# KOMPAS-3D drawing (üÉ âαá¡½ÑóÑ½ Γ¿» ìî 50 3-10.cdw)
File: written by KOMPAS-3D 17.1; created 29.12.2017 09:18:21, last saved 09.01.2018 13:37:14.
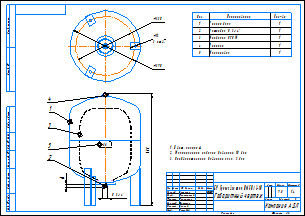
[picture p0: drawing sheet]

Sheet 1: A3, landscape, title-block layout from C:\Лощинин\GRAPHIC.LYT style 1

Title block, sheet 1: name: БР Гранлевел тип НМ 50/3-10 / Габаритный чертеж; mass: 9,8; sheets: 1; sheet format: A3; stored path: K:\АП\20_PKO\02_Насосное направление\Разработка\04_Проекты разные\Баки\КД действующая\Баки Flexcon R\Компас\Чертежи\БР Гранлевел тип НМ 50 1,5-6.cdw; drawn by: Лощинин; checked by: Хантимеров; drawn by, date: 29.12.2017

Views: Вид 1, Снизу
Referenced files in \\Fsk1\files\АП\20_PKO\02_Насосное направление\Разработка\04_Проекты разные\Баки\КД действующая\Баки Flexcon R\Компас\: 50 литров.a3d
Referenced files in C:\Лощинин\: GRAPHIC.LYT
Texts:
  IvAn
  ADL
  БР Гранлевел тип НМ 50/1,5-6
  Цвет: красный
  Максимальное рабочее давление: 10 бар
  Предварительное давление газа: 3 бар
  ACAD_ISO03W100_RGB_223_127_255_SC_0.063_THICK_0.05
  ACAD_ISO03W100_RGB_223_127_255_SC_1_THICK_0.05
  Лит-Масса-Масштаб
  Материал-Предприятие
  Масштаб
  Изм.
  Лист
  № докум.
  Подп.
  Дата
  Лит.
  Разраб.
  Пров.
  Т.контр.
  Курлыкина
  Листов
  Нач.отд.
  Щетинин
  Н.контр.
  Долгов
  Утв.
  Рашидов
  Компания АДЛ
  Изменение
  Номер документа
  Подпись
  Обозначение документа
  Наименование изделия
  Масса изделия по ГОСТ 2.109-73
  Порядковый номер листа
  Общее количество листов в документе
  Характер работы, выполненной лицом, подписавшим документ
  Наименование или индекс предприятия, выпускающего документ
  Инв. № подл.
  Подп. и дата
  Взам. инв. №
  Инв. № дубл.
  Инвентарный номер подлинника по ГОСТ 2.501-68
  Подпись принявшего подлинник в отдел технической документации
  Инвентарный номер подлинника, взамен которого выпущен данный подлинник
  Инвентарный номер дубликата по ГОСТ 2.502-68
  Подпись принявшего дубликат в отдел технической документации
  Справ. №
  Перв. примен.
  Обозначение документа, взамен или на основании которого выпущен данный документ
  Обозначение документа, в котором впервые записан данный документ
  Подпись лица, копировавшего чертеж
  Обозначение формата листа
Dimensions and other numbers on the sheet: 330; 390; 13; 3 отв.; 1:4; 1; 9,8; 29.12.2017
